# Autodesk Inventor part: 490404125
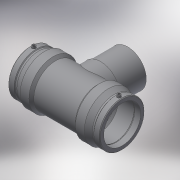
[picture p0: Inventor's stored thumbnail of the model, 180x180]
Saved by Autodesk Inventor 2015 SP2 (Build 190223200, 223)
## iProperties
Created: 2017-06
Part Number: 490404125
Material: Generic
Description: PLASSON TEE 125-125-125
Document SubType Name: Modeling
Designer: KIM
Mass: 3297.1 g
Surface Area: 4194.39 cm^2
Volume: 3297.1 cm^3
Density: 1 g/cm^3
Appearance: Default
Author: KIM
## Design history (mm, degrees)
derived "490404.ipt"
feature "Solid1::490404.ipt"
tag "TaggingFeature1"
body "Solid1"
other parameters: "d0" = 382, "d1" = 125, "d2" = 165, "d3" = 86, "d4" = 95.5, "d5" = 148.5, "d6" = 118.75, "d7" = 125, "d8" = 168 deg, "d10" = 34.4, "d11" = 11.46667, "d13" = 382, "d14" = 17.6296, "d17" = 112.5, "d18" = 125, "d19" = 3.52592, "d20" = 168 deg, "d22" = 153.45, "d23" = 165, "d24" = 148.8465, "d25" = 135 deg, "d26" = 267.4, "d27" = 135 deg, "d29" = 88, "d30" = 15, "d31" = 152.8, "d34" = 5 deg, "d35" = 15, "d39" = 5 deg, "d40" = 9.6, "d41" = 4.8, "d42" = 6, "d43" = 0, "d45" = 4, "d46" = 14, "d47" = 0, "d48" = -177, "d49" = 125, "d51" = 0, "d54" = 0, "d55" = 148.5, "d56" = 165, "d57" = 133.7, "d58" = 135 deg, "d59" = 86, "d60" = 86, "d61" = 135 deg, "d62" = 177, "d72" = 173.81, "d73" = 86.905, "d74" = -177, "d75" = 131.25, "d77" = 0, "d80" = 0, "d81" = 125, "d82" = 94.5, "d83" = 0, "d84" = 3, "d85" = 0, "d86" = 3, "d87" = 0, "d88" = 24.94, "d89" = 6.235, "d90" = 24.94, "d_" = 125, "L_" = 382, "L_1" = 86, "D_" = 165, "A_" = 88, "d_2" = 12, "H_" = 177
